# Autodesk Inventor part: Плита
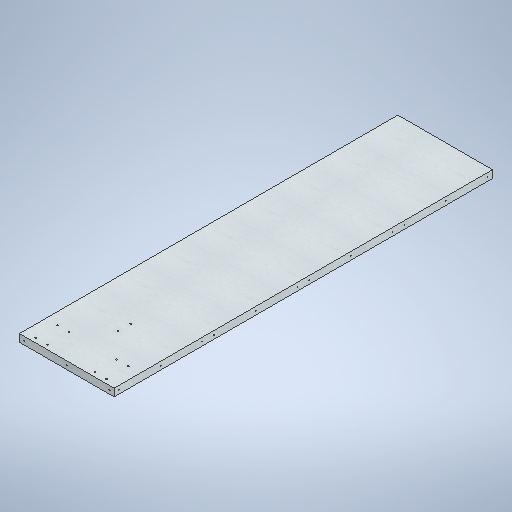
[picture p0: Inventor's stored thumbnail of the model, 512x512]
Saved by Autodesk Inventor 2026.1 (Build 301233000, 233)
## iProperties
Created: 2025-11
Part Number: Плита
Material: Типовые
Document SubType Name: Modeling
Designer: Yury Melnikov
Density: 1 g/cm^3
Appearance: Дерево — окрашенное — белое
Author: Yury Melnikov
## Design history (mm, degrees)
sketch "Эскиз1"
  geometry: L1 (0, 0)-(200, 0); L2 (200, 0)-(200, -16); L3 (200, -16)-(0, -16); L4 (0, -16)-(0, 0); 1 further point
  constraints: 8 end point, 2 parallel, 1 coincident, 1 horizontal, 1 perpendicular
  dimensions: "d0" = 200 distance of L2.end L3.end; "d1" = 16 distance of L1.end L2.end
extrude "Выдавливание1" new body sketch "Эскиз1" distance "d2" = 800; taper "d3" = 0 deg
sketch "Эскиз2"
  geometry: 1 further point
sketch "Эскиз3"
  geometry: L1 (802.124, 0)-(601.062, 0); L2 (601.062, 0)-(601.062, -16); L3 (601.062, -16)-(802.124, -16); L4 (802.124, -16)-(802.124, 0); L5 (601.062, 0)-(400, 0); L6 (400, 0)-(400, -16); L7 (400, -16)-(601.062, -16); L8 (601.062, -16)-(601.062, 0); L9 (400, 0)-(198.938, 0); L10 (198.938, 0)-(198.938, -16); L11 (198.938, -16)-(400, -16); L12 (400, -16)-(400, 0); L13 (198.938, 0)-(-2.124, 0); L14 (-2.124, 0)-(-2.124, -16); L15 (-2.124, -16)-(198.938, -16); L16 (198.938, -16)-(198.938, 0); L17 (800, 0)-(0, 0) reference; C1 r 1 at (789.558, -8); C2 r 1 at (701.613, -8); C3 r 1 at (613.668, -8); C4 r 1 at (588.496, -8); C5 r 1 at (500.551, -8); C6 r 1 at (412.606, -8); C7 r 1 at (387.434, -8); C8 r 1 at (299.489, -8); C9 r 1 at (211.544, -8); C10 r 1 at (186.372, -8); C11 r 1 at (98.427, -8); C12 r 1 at (10.482, -8); 5 further points
  constraints: 32 end point, 12 centre point, 3 horizontal, 2 midpoint, 2 parallel, 1 coincident, 1 collinear, 1 horizontal alignment, 1 perpendicular, 48 other
  dimensions: "d4" = 16 distance of L3.end L1.start; "d5" = 201.062 distance of L1.start L1.end; "d6" = 12.566 distance from line of L4 C1.centre; "d8" = 2 diameter of C1; "d11" = 87.945 distance of C1.centre C2.centre; "d18" = 201.062 distance of L1.start L5.start
extrude "Выдавливание2" cut sketch "Эскиз3" distance "d23" = 10; taper "d24" = 0 deg
node "РабПлоскость1"
mirror "Зеркальное отражение1"
sketch "Эскиз4"
  geometry: L1 (0, -16)-(200, -16) reference; L2 (200, -16)-(200, 0) reference; L3 (200, 0)-(0, 0) reference; L4 (0, 0)-(0, -16) reference; C1 r 1.5 at (10, -8); C2 r 1.5 at (100, -8); C3 r 1.5 at (190, -8); 2 further points
  constraints: 3 centre point, 1 horizontal, 1 horizontal alignment, 1 midpoint, 4 other
  dimensions: "d25" = 3 diameter of C1; "d26" = 10 distance from line of L4 C1.centre; "d29" = 90 distance of C1.centre C2.centre (derived); "d34" = 10 distance from line of L2 C3.centre
extrude "Выдавливание3" cut sketch "Эскиз4" distance "d35" = 100; taper "d36" = 0 deg
sketch "Эскиз5"
  geometry: L1 (25, -745)-(50, -745); L2 (50, -745)-(50, -791); L3 (50, -791)-(25, -791); L4 (25, -791)-(25, -745); L5 (200, -800)-(0, -800) reference; L6 (0, 0)-(0, -800) reference; L7 (100, -800)-(100, -756.623); L8 (175, -745)-(150, -745); L9 (150, -745)-(150, -791); L10 (150, -791)-(175, -791); L11 (175, -791)-(175, -745); C1 r 1.5 at (25, -745); C2 r 1.5 at (50, -745); C3 r 1.5 at (25, -791); C4 r 1.5 at (50, -791); C5 r 1.5 at (175, -745); C6 r 1.5 at (150, -745); C7 r 1.5 at (175, -791); C8 r 1.5 at (150, -791)
  constraints: 18 end point, 8 centre point, 8 symmetric about line, 2 coincident, 2 horizontal, 2 parallel, 2 vertical, 1 midpoint, 1 perpendicular, 10 other
  dimensions: "d37" = 46 distance of L1.end L2.end; "d38" = 25 distance of L1.start L1.end; "d39" = 3 diameter of C1; "d42" = 25 distance of C1.centre C2.centre; "d45" = 46 distance of C1.centre C3.centre; "d48" = 9 distance between parallel lines of L5 L3; "d49" = 25 distance between parallel lines of L4 L6
extrude "Выдавливание4" cut sketch "Эскиз5" distance "d50" = 15; taper "d51" = 0 deg
sketch "Эскиз6"
  geometry: L1 (200, -800)-(0, -800) reference; C1 r 1.5 at (100, -691.569); C2 r 1.5 at (100, -665); 2 further points
  constraints: 2 centre point, 2 vertical alignment, 1 equal radius, 1 midpoint
  dimensions: "d52" = 3 diameter of C1; "d53" = 135 distance from line of L1 C2.centre; "d54" = 26.569 distance of C1.centre C2.centre
extrude "Выдавливание5" cut sketch "Эскиз6" distance "d55" = 16; taper "d56" = 0 deg
node "Твердое тело1"
node "Эскиз — прямоугольный массив1" dims "d11" = 87.945, "d14" = 10
node "Эскиз — прямоугольный массив2" dims "d18" = 201.062, "d21" = 10
node "Спроецированная петля1"
node "Эскиз — прямоугольный массив3" dims "d29" = 90 (derived), "d32" = 10
node "Эскиз — прямоугольный массив4" dims "d42" = 25, "d45" = 46
